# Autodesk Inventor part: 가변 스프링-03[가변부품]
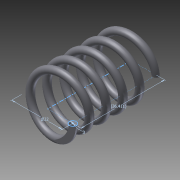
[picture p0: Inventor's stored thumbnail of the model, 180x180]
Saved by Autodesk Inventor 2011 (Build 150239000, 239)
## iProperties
Created: 2015-05
Part Number: 가변 스프링-03[가변부품]
Document SubType Name: Modeling
Designer: Administrator
Density: 7.87 g/cm^3
Mass: 18.9242 g
Surface Area: 32.5548 cm^2
Volume: 2.40459 cm^3
Material: 탄소강
Author: Administrator
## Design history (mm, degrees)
sketch "스케치1"
  geometry: L1 (0, 0)-(11, 0); L2 (11, 0)-(11, 36.411); L3 (11, 36.411)-(0, 36.411); L4 (0, 36.411)-(0, 0); C1 r 1.5 at (11, 0)
  constraints: 8 end point, 2 parallel, 1 centre point, 1 coincident, 1 horizontal, 1 perpendicular
  dimensions: "d0" = 22 diameter of L2 L4; "d1" = 3 diameter of C1; "d2" = 36.4112 distance of L1.end L2.end (derived)
feature "코일1" pitch "d3" = 10; turns "d5" = 5; dims "d4" = 36.4112 (= d2), "d6" = 0, angle "d7" = 90 deg, angle "d8" = 90 deg, "d9" = 0, "d10" = 0
sketch "스케치2"
  geometry: L1 (-12.5, 0)-(-9.5, 0) reference; 1 further point
  constraints: 1 horizontal alignment
extrude "돌출1" cut sketch "스케치2" stored distance "d11" = 10; taper "d12" = 0 deg
node "작업 평면1"
sketch "스케치3"
  geometry: L1 (1.5, 0)-(-1.5, 0) reference; 1 further point
  constraints: 1 horizontal alignment
extrude "돌출2" cut sketch "스케치3" stored distance "d13" = 10; taper "d14" = 0 deg
node "솔리드1"
node "절단 모서리 투영1"
node "절단 모서리 투영2"
